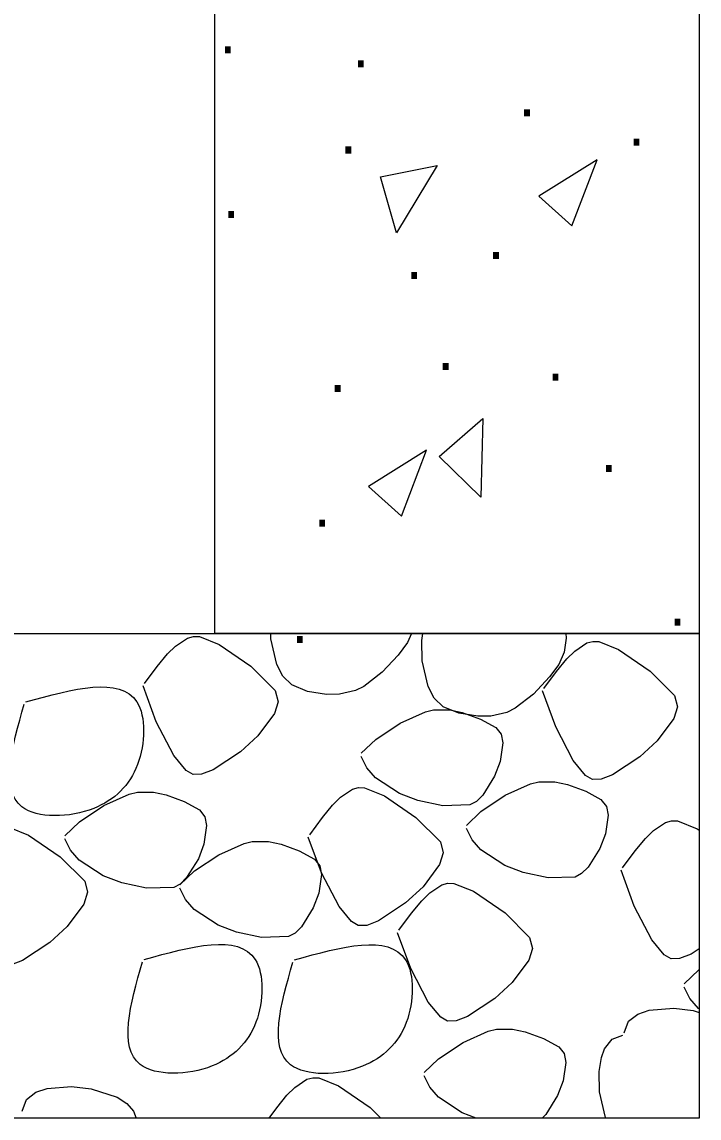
# Model space of a CAD drawing. Extents: x 638447 to 639352, y 298406 to 299000.
# Drawn here: x 638776.97 to 638793.75, y 298690 to 298717.15 of the extents above; entities that cross this region are included whole.
import ezdxf

# ---------------------------------------------------------------- set-up
doc = ezdxf.new("R2010")
doc.units = 0
doc.layers.add('2', color=7, linetype='Continuous')

msp = doc.modelspace()

# ---------------------------------------------------------------- linework, layer by layer
at = {"layer": '2'}
for points in [[(638787.754375, 298774.004), (638793.754375, 298774.004), (638793.754375, 298702.004), (638781.754375, 298702.004), (638781.754375, 298766.248)], [(638780.776375, 298701.692), (638781.074375, 298701.89)], [(638781.074375, 298701.89), (638781.222375, 298701.932)], [(638781.222375, 298701.932), (638781.370375, 298701.926)], [(638781.370375, 298701.926), (638781.860375, 298701.73)], [(638783.144375, 298701.87), (638783.142375, 298702.004)], [(638783.292375, 298701.234), (638783.144375, 298701.87)], [(638786.626375, 298702.004), (638786.528375, 298701.776)], [(638786.884375, 298701.83), (638786.910375, 298702.004)], [(638786.894375, 298701.328), (638786.884375, 298701.83)], [(638790.456375, 298701.888), (638790.408375, 298701.54)], [(638790.452375, 298702.004), (638790.456375, 298701.888)], [(638790.972375, 298701.768), (638791.120375, 298701.808)], [(638791.120375, 298701.808), (638791.268375, 298701.802)], [(638791.268375, 298701.802), (638791.758375, 298701.606)], [(638780.578375, 298701.496), (638780.776375, 298701.692)], [(638781.860375, 298701.73), (638782.644375, 298701.192)], [(638786.528375, 298701.776), (638786.300375, 298701.466)], [(638790.408375, 298701.54), (638790.278375, 298701.236)], [(638790.476375, 298701.372), (638790.674375, 298701.568)], [(638790.674375, 298701.568), (638790.972375, 298701.768)], [(638791.758375, 298701.606), (638792.542375, 298701.068)], [(638780.324375, 298701.188), (638780.578375, 298701.496)], [(638786.300375, 298701.466), (638785.898375, 298701.044)], [(638787.042375, 298700.692), (638786.894375, 298701.328)], [(638790.222375, 298701.064), (638790.476375, 298701.372)], [(638780.012375, 298700.762), (638780.324375, 298701.188)], [(638782.644375, 298701.192), (638783.250375, 298700.588)], [(638783.440375, 298700.944), (638783.292375, 298701.234)], [(638785.898375, 298701.044), (638785.442375, 298700.692)], [(638789.910375, 298700.638), (638790.222375, 298701.064)], [(638790.278375, 298701.236), (638790.050375, 298700.926)], [(638792.542375, 298701.068), (638793.148375, 298700.464)], [(638780.302375, 298699.818), (638779.974375, 298700.704)], [(638783.658375, 298700.73), (638783.440375, 298700.944)], [(638784.052375, 298700.57), (638783.658375, 298700.73)], [(638790.050375, 298700.926), (638789.648375, 298700.502)], [(638783.250375, 298700.588), (638783.320375, 298700.314)], [(638784.520375, 298700.492), (638784.052375, 298700.57)], [(638784.842375, 298700.498), (638784.520375, 298700.492)], [(638785.242375, 298700.59), (638784.842375, 298700.498)], [(638785.442375, 298700.692), (638785.242375, 298700.59)], [(638787.190375, 298700.404), (638787.042375, 298700.692)], [(638789.648375, 298700.502), (638789.192375, 298700.15)], [(638790.200375, 298699.694), (638789.872375, 298700.58)], [(638793.148375, 298700.464), (638793.218375, 298700.19)], [(638783.320375, 298700.314), (638783.228375, 298700.024)], [(638787.408375, 298700.188), (638787.190375, 298700.404)], [(638787.802375, 298700.028), (638787.408375, 298700.188)], [(638793.218375, 298700.19), (638793.126375, 298699.9)], [(638783.228375, 298700.024), (638782.818375, 298699.468)], [(638786.346375, 298699.784), (638786.970375, 298700.066)], [(638786.970375, 298700.066), (638787.174375, 298700.116)], [(638787.174375, 298700.116), (638787.574375, 298700.112)], [(638787.574375, 298700.112), (638787.886375, 298700.048)], [(638788.270375, 298699.952), (638787.802375, 298700.028)], [(638787.886375, 298700.048), (638788.336375, 298699.882)], [(638788.590375, 298699.958), (638788.270375, 298699.952)], [(638788.336375, 298699.882), (638788.714375, 298699.678)], [(638788.992375, 298700.048), (638788.590375, 298699.958)], [(638789.192375, 298700.15), (638788.992375, 298700.048)], [(638793.126375, 298699.9), (638792.716375, 298699.344)], [(638780.738375, 298698.984), (638780.302375, 298699.818)], [(638785.740375, 298699.382), (638786.346375, 298699.784)], [(638788.714375, 298699.678), (638788.850375, 298699.508)], [(638790.636375, 298698.86), (638790.200375, 298699.694)], [(638782.818375, 298699.468), (638782.386375, 298699.072)], [(638785.380375, 298699.038), (638785.740375, 298699.382)], [(638788.850375, 298699.508), (638788.890375, 298699.292)], [(638792.716375, 298699.344), (638792.284375, 298698.948)], [(638782.386375, 298699.072), (638781.712375, 298698.628)], [(638788.890375, 298699.292), (638788.824375, 298698.832)], [(638781.044375, 298698.614), (638780.738375, 298698.984)], [(638785.520375, 298698.678), (638785.380375, 298698.96)], [(638788.824375, 298698.832), (638788.686375, 298698.468)], [(638790.942375, 298698.49), (638790.636375, 298698.86)], [(638792.284375, 298698.948), (638791.610375, 298698.504)], [(638781.214375, 298698.514), (638781.044375, 298698.614)], [(638781.712375, 298698.628), (638781.426375, 298698.52)], [(638785.736375, 298698.43), (638785.520375, 298698.678)], [(638781.426375, 298698.52), (638781.214375, 298698.514)], [(638786.328375, 298698.042), (638785.736375, 298698.43)], [(638788.686375, 298698.468), (638788.396375, 298698)], [(638788.952375, 298697.998), (638789.578375, 298698.28)], [(638789.578375, 298698.28), (638789.782375, 298698.33)], [(638789.782375, 298698.33), (638790.182375, 298698.326)], [(638790.182375, 298698.326), (638790.494375, 298698.262)], [(638790.494375, 298698.262), (638790.944375, 298698.098)], [(638791.112375, 298698.39), (638790.942375, 298698.49)], [(638791.324375, 298698.396), (638791.112375, 298698.39)], [(638791.610375, 298698.504), (638791.324375, 298698.396)], [(638779.004375, 298697.742), (638779.628375, 298698.024)], [(638779.628375, 298698.024), (638779.834375, 298698.076)], [(638779.834375, 298698.076), (638780.232375, 298698.072)], [(638780.232375, 298698.072), (638780.544375, 298698.006)], [(638780.544375, 298698.006), (638780.996375, 298697.842)], [(638784.870375, 298697.948), (638785.168375, 298698.148)], [(638785.168375, 298698.148), (638785.316375, 298698.19)], [(638785.316375, 298698.19), (638785.464375, 298698.184)], [(638785.464375, 298698.184), (638785.954375, 298697.986)], [(638785.954375, 298697.986), (638786.738375, 298697.448)], [(638786.786375, 298697.866), (638786.328375, 298698.042)], [(638788.396375, 298698), (638788.234375, 298697.842)], [(638788.348375, 298697.598), (638788.952375, 298697.998)], [(638790.944375, 298698.098), (638791.322375, 298697.892)], [(638778.400375, 298697.342), (638779.004375, 298697.742)], [(638780.996375, 298697.842), (638781.374375, 298697.636)], [(638784.418375, 298697.446), (638784.672375, 298697.752)], [(638784.672375, 298697.752), (638784.870375, 298697.948)], [(638787.402375, 298697.738), (638786.786375, 298697.866)], [(638788.074375, 298697.758), (638787.402375, 298697.738)], [(638788.234375, 298697.842), (638788.074375, 298697.758)], [(638791.322375, 298697.892), (638791.458375, 298697.722)], [(638791.458375, 298697.722), (638791.498375, 298697.506)], [(638781.374375, 298697.636), (638781.508375, 298697.466)], [(638781.508375, 298697.466), (638781.550375, 298697.252)], [(638784.106375, 298697.02), (638784.418375, 298697.446)], [(638786.738375, 298697.448), (638787.344375, 298696.846)], [(638787.988375, 298697.252), (638788.348375, 298697.598)], [(638791.498375, 298697.506), (638791.432375, 298697.046)], [(638776.648375, 298697.206), (638777.138375, 298697.008)], [(638778.038375, 298696.996), (638778.400375, 298697.342)], [(638781.550375, 298697.252), (638781.484375, 298696.79)], [(638788.128375, 298696.892), (638787.988375, 298697.174)], [(638792.622375, 298697.126), (638792.920375, 298697.326)], [(638792.920375, 298697.326), (638793.068375, 298697.368)], [(638793.068375, 298697.368), (638793.216375, 298697.362)], [(638793.216375, 298697.362), (638793.706375, 298697.164)], [(638777.138375, 298697.008), (638777.922375, 298696.47)], [(638778.178375, 298696.636), (638778.038375, 298696.92)], [(638784.396375, 298696.076), (638784.068375, 298696.962)], [(638791.432375, 298697.046), (638791.294375, 298696.682)], [(638792.172375, 298696.624), (638792.424375, 298696.93)], [(638792.424375, 298696.93), (638792.622375, 298697.126)], [(638793.706375, 298697.164), (638793.754375, 298697.132)], [(638778.394375, 298696.39), (638778.178375, 298696.636)], [(638781.484375, 298696.79), (638781.346375, 298696.426)], [(638781.852375, 298696.524), (638782.478375, 298696.806)], [(638782.478375, 298696.806), (638782.682375, 298696.856)], [(638782.682375, 298696.856), (638783.080375, 298696.852)], [(638783.080375, 298696.852), (638783.394375, 298696.788)], [(638783.394375, 298696.788), (638783.844375, 298696.624)], [(638787.344375, 298696.846), (638787.414375, 298696.572)], [(638788.344375, 298696.644), (638788.128375, 298696.892)], [(638788.936375, 298696.256), (638788.344375, 298696.644)], [(638791.294375, 298696.682), (638791.004375, 298696.214)], [(638777.922375, 298696.47), (638778.528375, 298695.868)], [(638778.986375, 298696.002), (638778.394375, 298696.39)], [(638781.346375, 298696.426), (638781.054375, 298695.96)], [(638781.248375, 298696.124), (638781.852375, 298696.524)], [(638783.844375, 298696.624), (638784.222375, 298696.418)], [(638784.222375, 298696.418), (638784.356375, 298696.248)], [(638787.414375, 298696.572), (638787.322375, 298696.282)], [(638791.858375, 298696.198), (638792.172375, 298696.624)], [(638780.888375, 298695.778), (638781.248375, 298696.124)], [(638784.356375, 298696.248), (638784.398375, 298696.032)], [(638787.322375, 298696.282), (638786.912375, 298695.726)], [(638789.394375, 298696.082), (638788.936375, 298696.256)], [(638790.010375, 298695.952), (638789.394375, 298696.082)], [(638791.004375, 298696.214), (638790.842375, 298696.056)], [(638792.148375, 298695.254), (638791.820375, 298696.14)], [(638778.528375, 298695.868), (638778.600375, 298695.594)], [(638779.446375, 298695.826), (638778.986375, 298696.002)], [(638780.060375, 298695.696), (638779.446375, 298695.826)], [(638781.054375, 298695.96), (638780.892375, 298695.8)], [(638784.398375, 298696.032), (638784.332375, 298695.572)], [(638784.832375, 298695.242), (638784.396375, 298696.076)], [(638787.378375, 298695.782), (638787.528375, 298695.824)], [(638787.528375, 298695.824), (638787.674375, 298695.816)], [(638787.674375, 298695.816), (638788.164375, 298695.62)], [(638790.682375, 298695.972), (638790.010375, 298695.952)], [(638790.842375, 298696.056), (638790.682375, 298695.972)], [(638778.600375, 298695.594), (638778.508375, 298695.304)], [(638780.734375, 298695.716), (638780.060375, 298695.696)], [(638780.892375, 298695.8), (638780.734375, 298695.716)], [(638781.028375, 298695.418), (638780.888375, 298695.7)], [(638784.332375, 298695.572), (638784.194375, 298695.208)], [(638786.912375, 298695.726), (638786.480375, 298695.33)], [(638786.884375, 298695.386), (638787.080375, 298695.582)], [(638787.080375, 298695.582), (638787.378375, 298695.782)], [(638788.164375, 298695.62), (638788.948375, 298695.082)], [(638778.508375, 298695.304), (638778.096375, 298694.748)], [(638781.242375, 298695.17), (638781.028375, 298695.418)], [(638786.480375, 298695.33), (638785.806375, 298694.886)], [(638786.630375, 298695.08), (638786.884375, 298695.386)], [(638781.834375, 298694.784), (638781.242375, 298695.17)], [(638784.194375, 298695.208), (638783.904375, 298694.74)], [(638785.138375, 298694.872), (638784.832375, 298695.242)], [(638786.316375, 298694.654), (638786.630375, 298695.08)], [(638788.948375, 298695.082), (638789.554375, 298694.478)], [(638792.584375, 298694.42), (638792.148375, 298695.254)], [(638778.096375, 298694.748), (638777.666375, 298694.352)], [(638782.294375, 298694.608), (638781.834375, 298694.784)], [(638783.904375, 298694.74), (638783.742375, 298694.582)], [(638785.308375, 298694.77), (638785.138375, 298694.872)], [(638785.520375, 298694.776), (638785.308375, 298694.77)], [(638785.806375, 298694.886), (638785.520375, 298694.776)], [(638782.910375, 298694.478), (638782.294375, 298694.608)], [(638783.582375, 298694.498), (638782.910375, 298694.478)], [(638783.742375, 298694.582), (638783.582375, 298694.498)], [(638786.608375, 298693.71), (638786.278375, 298694.594)], [(638789.554375, 298694.478), (638789.626375, 298694.206)], [(638777.666375, 298694.352), (638776.990375, 298693.908)], [(638789.626375, 298694.206), (638789.534375, 298693.914)], [(638792.890375, 298694.05), (638792.584375, 298694.42)], [(638793.754375, 298694.192), (638793.558375, 298694.064)], [(638789.534375, 298693.914), (638789.122375, 298693.36)], [(638793.060375, 298693.948), (638792.890375, 298694.05)], [(638793.272375, 298693.954), (638793.060375, 298693.948)], [(638793.558375, 298694.064), (638793.272375, 298693.954)], [(638776.990375, 298693.908), (638776.704375, 298693.798)], [(638787.042375, 298692.876), (638786.608375, 298693.71)], [(638793.388375, 298693.326), (638793.748375, 298693.672)], [(638793.748375, 298693.672), (638793.754375, 298693.676)], [(638789.122375, 298693.36), (638788.692375, 298692.962)], [(638793.528375, 298692.966), (638793.388375, 298693.248)], [(638787.350375, 298692.506), (638787.042375, 298692.876)], [(638788.692375, 298692.962), (638788.016375, 298692.518)], [(638793.742375, 298692.718), (638793.528375, 298692.966)], [(638792.006375, 298692.406), (638792.238375, 298692.58)], [(638792.238375, 298692.58), (638792.520375, 298692.676)], [(638792.520375, 298692.676), (638793.124375, 298692.724)], [(638793.124375, 298692.724), (638793.606375, 298692.668)], [(638793.606375, 298692.668), (638793.754375, 298692.62)], [(638793.754375, 298692.712), (638793.742375, 298692.718)], [(638787.520375, 298692.404), (638787.350375, 298692.506)], [(638787.730375, 298692.41), (638787.520375, 298692.404)], [(638788.016375, 298692.518), (638787.730375, 298692.41)], [(638791.900375, 298692.112), (638792.006375, 298692.406)], [(638787.904375, 298691.876), (638788.528375, 298692.158)], [(638788.528375, 298692.158), (638788.734375, 298692.208)], [(638788.734375, 298692.208), (638789.132375, 298692.204)], [(638789.132375, 298692.204), (638789.444375, 298692.14)], [(638789.444375, 298692.14), (638789.896375, 298691.974)], [(638791.596375, 298691.96), (638791.862375, 298692.054)], [(638787.300375, 298691.474), (638787.904375, 298691.876)], [(638789.896375, 298691.974), (638790.274375, 298691.77)], [(638790.274375, 298691.77), (638790.408375, 298691.6)], [(638791.412375, 298691.722), (638791.596375, 298691.96)], [(638786.940375, 298691.13), (638787.300375, 298691.474)], [(638790.408375, 298691.6), (638790.450375, 298691.384)], [(638791.278375, 298691.156), (638791.334375, 298691.502)], [(638791.334375, 298691.502), (638791.412375, 298691.722)], [(638790.450375, 298691.384), (638790.384375, 298690.924)], [(638783.736375, 298690.764), (638784.034375, 298690.964)], [(638784.034375, 298690.964), (638784.182375, 298691.004)], [(638784.182375, 298691.004), (638784.330375, 298690.998)], [(638784.330375, 298690.998), (638784.820375, 298690.802)], [(638787.078375, 298690.77), (638786.940375, 298691.052)], [(638791.288375, 298690.654), (638791.278375, 298691.156)], [(638777.318375, 298690.644), (638777.602375, 298690.74)], [(638777.602375, 298690.74), (638778.204375, 298690.786)], [(638778.204375, 298690.786), (638778.686375, 298690.732)], [(638778.686375, 298690.732), (638779.332375, 298690.52)], [(638783.538375, 298690.568), (638783.736375, 298690.764)], [(638784.820375, 298690.802), (638785.604375, 298690.264)], [(638787.294375, 298690.522), (638787.078375, 298690.77)], [(638790.384375, 298690.924), (638790.246375, 298690.56)], [(638791.438375, 298690.018), (638791.288375, 298690.654)], [(638776.980375, 298690.176), (638777.086375, 298690.468)], [(638777.086375, 298690.468), (638777.318375, 298690.644)], [(638779.332375, 298690.52), (638779.574375, 298690.362)], [(638783.286375, 298690.26), (638783.538375, 298690.568)], [(638787.886375, 298690.134), (638787.294375, 298690.522)], [(638790.246375, 298690.56), (638789.954375, 298690.092)], [(638779.574375, 298690.362), (638779.734375, 298690.176)], [(638779.734375, 298690.176), (638779.800375, 298690.004)], [(638783.096375, 298690.004), (638783.286375, 298690.26)], [(638785.604375, 298690.264), (638785.864375, 298690.004)], [(638788.228375, 298690.004), (638787.886375, 298690.134)], [(638789.954375, 298690.092), (638789.864375, 298690.004)], [(638791.446375, 298690.004), (638791.438375, 298690.018)]]:
    msp.add_lwpolyline(points, dxfattribs=at)
for points in [[(638791.226375, 298713.732), (638789.786375, 298712.832), (638790.602375, 298712.1)], [(638785.862375, 298713.312), (638787.266375, 298713.588), (638786.258375, 298711.92)], [(638787.314375, 298706.388), (638788.394375, 298707.324), (638788.346375, 298705.38)], [(638787.002375, 298706.544), (638785.562375, 298705.644), (638786.378375, 298704.912)], [(638721.754375, 298690.004), (638721.754375, 298702.004), (638793.754375, 298702.004), (638793.754375, 298690.004)]]:
    msp.add_lwpolyline(points, close=True, dxfattribs=at)
for points in [[(638777.066375, 298700.31), (638779.820375, 298700.31), (638779.838375, 298698.758), (638778.752375, 298697.672), (638776.970375, 298697.712), (638777.028375, 298700.252)], [(638780.000375, 298693.932), (638782.752375, 298693.932), (638782.772375, 298692.38), (638781.686375, 298691.294), (638779.902375, 298691.334), (638779.960375, 298693.874)], [(638783.726375, 298693.924), (638786.478375, 298693.924), (638786.498375, 298692.374), (638785.412375, 298691.288), (638783.628375, 298691.326), (638783.686375, 298693.866)]]:
    msp.add_spline(points, degree=3, dxfattribs=at)

# ---------------------------------------------------------------- texts
for p in [(638781.866375, 298716.372), (638785.166375, 298716.024), (638789.282375, 298714.812), (638784.854375, 298713.888), (638784.854375, 298713.888), (638791.994375, 298714.08), (638781.950375, 298712.292), (638788.514375, 298711.272), (638786.486375, 298710.78), (638787.266375, 298708.524), (638789.990375, 298708.26), (638784.590375, 298707.984), (638791.310375, 298706.004), (638784.206375, 298704.648), (638793.014375, 298702.2), (638783.654375, 298701.768)]:
    msp.add_text('.', height=1.116, dxfattribs=at).set_placement(p)

doc.saveas('drawing.dxf')
